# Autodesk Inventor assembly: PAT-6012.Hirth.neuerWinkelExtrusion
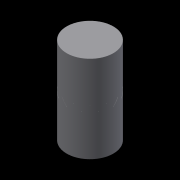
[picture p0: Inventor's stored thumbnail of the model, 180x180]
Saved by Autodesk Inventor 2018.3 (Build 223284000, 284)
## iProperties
Created: 2020-03
Part Number: PAT-6012.Hirth.neuerWinkelExtrusion
Document SubType Name: Assembly
Designer: Th. Mörgeli
Mass: 35.3412 g
Surface Area: 96.8614 cm^2
Volume: 35.3412 cm^3
Density: 1 g/cm^3
Author: Th. Mörgeli
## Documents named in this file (2)
- C:\Users\mothomas\Documents\Inventor\Patterson\PATHirth.neuerWinkelExtrusion.iam
- C:\Users\mothomas\Documents\Inventor\Patterson\PATHirth.neuerWinkelExtrusion.ipt
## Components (2 placed, 1 different names)
1. PATHirth.neuerWinkelExtrusion:1 — Mate:1, Mate:2, Angle:1
2. PATHirth.neuerWinkelExtrusion:2 — Mate:1, Mate:2, Angle:1
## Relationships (3: Mate 2, Angle 1)
- Mate:1: PATHirth.neuerWinkelExtrusion:1 ↔ PATHirth.neuerWinkelExtrusion:2
- Mate:2: PATHirth.neuerWinkelExtrusion:1 ↔ PATHirth.neuerWinkelExtrusion:2
- Angle:1: PATHirth.neuerWinkelExtrusion:1 ↔ PATHirth.neuerWinkelExtrusion:2
